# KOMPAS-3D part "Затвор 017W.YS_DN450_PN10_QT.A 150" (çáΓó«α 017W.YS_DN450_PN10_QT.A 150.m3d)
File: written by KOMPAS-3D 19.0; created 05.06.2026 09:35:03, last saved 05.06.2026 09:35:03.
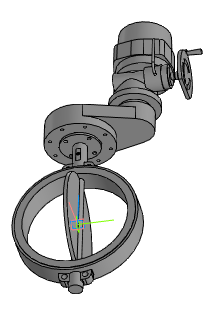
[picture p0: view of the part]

Document properties: Автор: Энергия; Полное имя файла: ..\..\..\3d для проектировщиков\x.x Тип 017W.Y(S) Затвор дисковый поворотный межфланцевый\Затвор 017W.Y(S)_DN32-DN1200_QT.A_MT903.A\Затвор 017W.YS_DN450_PN10_QT.A 150.a3d

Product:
- Part/product: Затвор 017W.YS_DN450_PN10_QT.A 150
    Масса: 274.106

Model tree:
1. Операция без истории:1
